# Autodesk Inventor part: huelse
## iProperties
Created: 2004-12
Part Number: huelse
Document SubType Name: Modeling
Designer: marocsikf
Manufacturer: Standard
Standards Organization: Custom
Author: marocsikf
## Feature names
1. Drehung1 [Revolution]
